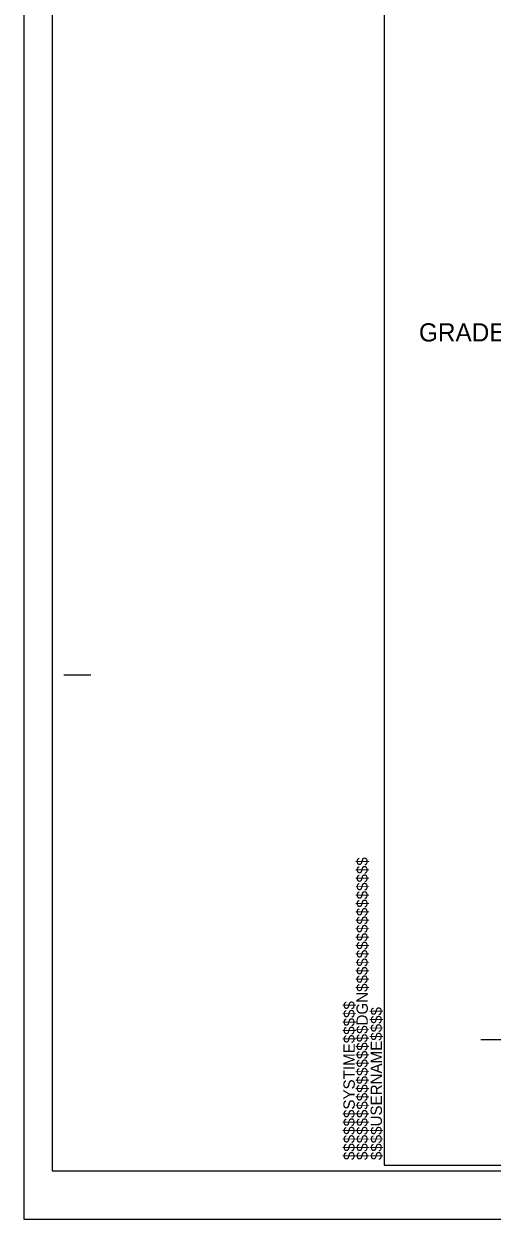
# Model space of a CAD drawing. Extents: x 574067 to 574470, y -53282 to -53062.
# Drawn here: x 574066.9 to 574110.3, y -53282.1 to -53171.2 of the extents above; entities that cross this region are included whole.
import ezdxf

# ---------------------------------------------------------------- set-up
doc = ezdxf.new("R2010")
doc.units = 0
for name, color, linetype in [('Old_Level_1', 7, 'Continuous'), ('Sheet Cutting Line CELL', 7, 'Continuous'), ('Sheet Plot Border Inside CELL', 7, 'Continuous'), ('Sheet Plot Border Outside CELL', 7, 'Continuous'), ('Sheet Typical CELL', 7, 'Continuous'), ('Typical Text General CELL', 7, 'Continuous')]:
    doc.layers.add(name, color=color, linetype=linetype)

msp = doc.modelspace()

# ---------------------------------------------------------------- linework, layer by layer
at = {"layer": 'Sheet Cutting Line CELL'}
for p, q in [((574066.93, -53062.12), (574066.93, -53282.12)), ((574066.93, -53282.12), (574403.73, -53282.12))]:
    msp.add_line(p, q, dxfattribs=at)
at = {"layer": 'Sheet Plot Border Inside CELL'}
msp.add_lwpolyline([(574402.83, -53066.61), (574069.53, -53066.61), (574069.53, -53277.63), (574402.83, -53277.63)], close=True, dxfattribs=at)
at = {"layer": 'Sheet Plot Border Outside CELL'}
msp.add_lwpolyline([(574403.73, -53062.12), (574066.93, -53062.12), (574066.93, -53282.12), (574403.73, -53282.12)], close=True, dxfattribs=at)
at = {"layer": 'Sheet Typical CELL'}
for p, q in [((574070.63, -53231.62), (574073.13, -53231.62)), ((574100.33, -53277.12), (574100.33, -53277.12)), ((574100.33, -53277.12), (574100.33, -53277.12)), ((574100.33, -53277.12), (574100.33, -53277.12)), ((574100.33, -53277.12), (574100.33, -53277.12)), ((574100.33, -53277.12), (574100.33, -53277.12)), ((574100.33, -53277.12), (574100.33, -53277.12))]:
    msp.add_line(p, q, dxfattribs=at)
msp.add_lwpolyline([(574400.33, -53067.12), (574100.33, -53067.12), (574100.33, -53277.12), (574400.33, -53277.12)], close=True, dxfattribs=at)
msp.add_lwpolyline([(574107.83, -53277.12), (574107.83, -53277.12)], dxfattribs=at)
at = {"layer": 'Typical Text General CELL'}
msp.add_line((574109.27, -53265.46), (574193.94, -53265.46), dxfattribs=at)

# ---------------------------------------------------------------- texts
at = {"layer": 'Old_Level_1'}
msp.add_text('GRADE TO THIS LINE', height=1.6875, dxfattribs=at).set_placement((574103.54, -53200.67))
at = {"layer": 'Sheet Typical CELL'}
for s, p in [('$$$$$$$$$$$$$$$$DGN$$$$$$$$$$$$$$$$', (574098.8, -53276.65)), ('$$$$$$SYSTIME$$$$$', (574097.59, -53276.65)), ('$$$$USERNAME$$$$', (574100.11, -53276.65))]:
    msp.add_text(s, height=1.05, rotation=90, dxfattribs=at).set_placement(p)

doc.saveas('drawing.dxf')
